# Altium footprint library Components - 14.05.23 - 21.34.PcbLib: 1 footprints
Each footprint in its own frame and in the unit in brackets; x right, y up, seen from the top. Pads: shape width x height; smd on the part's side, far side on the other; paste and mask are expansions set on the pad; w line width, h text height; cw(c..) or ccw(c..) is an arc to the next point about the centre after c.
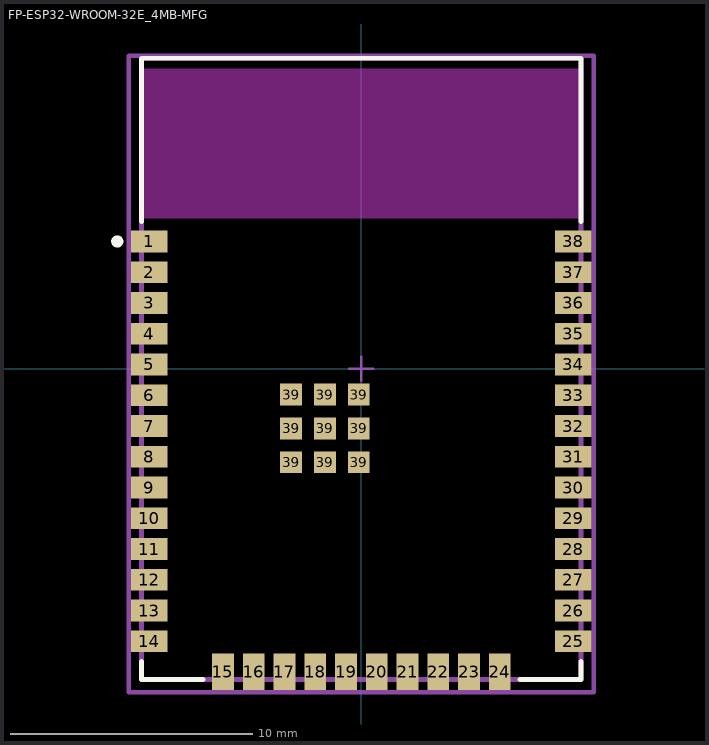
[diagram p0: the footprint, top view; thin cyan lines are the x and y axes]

## FP-ESP32-WROOM-32E_4MB-MFG [mm]
pads (47):
  rect 1.5x0.9 smd paste+0 mask+0: 1(-8.75,5.26) 2(-8.75,3.99) 3(-8.75,2.72) 4(-8.75,1.45) 5(-8.75,0.18) 6(-8.75,-1.09) 7(-8.75,-2.36) 8(-8.75,-3.63) 9(-8.75,-4.9) 10(-8.75,-6.17) 11(-8.75,-7.44) 12(-8.75,-8.71) 13(-8.75,-9.98) 14(-8.75,-11.25) 25(8.75,-11.25) 26(8.75,-9.98) 27(8.75,-8.71) 28(8.75,-7.44) 29(8.75,-6.17) 30(8.75,-4.9) 31(8.75,-3.63) 32(8.75,-2.36) 33(8.75,-1.09) 34(8.75,0.18) 35(8.75,1.45) 36(8.75,2.72) 37(8.75,3.99) 38(8.75,5.26)
  rect 0.9x1.5 smd paste+0 mask+0: 15(-5.71,-12.5) 16(-4.44,-12.5) 17(-3.17,-12.5) 18(-1.9,-12.5) 19(-0.63,-12.5) 20(0.64,-12.5) 21(1.91,-12.5) 22(3.18,-12.5) 23(4.45,-12.5) 24(5.72,-12.5)
  rect 0.9x0.9 smd paste+0 mask+0: 39(-2.9,-3.86) 39(-2.9,-2.46) 39(-2.9,-1.06) 39(-1.5,-3.86) 39(-1.5,-2.46) 39(-1.5,-1.06) 39(-0.1,-3.86) 39(-0.1,-2.46) 39(-0.1,-1.06)
Top Overlay:
  circle w0.25: c-10.075,5.26 r0.125
  lines w0.2: -9.075,-12.075 -9.075,-12.825 -6.535,-12.825 ; -9.075,6.085 -9.075,12.825 9.075,12.825 9.075,6.085 ; 6.545,-12.825 9.075,-12.825 9.075,-12.075
Keep-Out Layer:
  rectangle: -9,6.205 9,12.395
  rectangle: -9,6.205 9,12.395
Top Assembly:
  lines w0.2: -9.6,-13.35 -9.6,12.925 9.6,12.925 9.6,-13.35 -9.6,-13.35
  text ".Designator" at 0,-0.025 h1
Top 3D Body:
  lines w0.2: -9.075,-12.825 -9.075,12.825 9.075,12.825 9.075,-12.825 -9.075,-12.825
Top Courtyard:
  lines w0.2: -9.6,-13.35 -9.6,12.925 9.6,12.925 9.6,-13.35 -9.6,-13.35
Top Component Center:
  lines w0.1: -0.5,0 0.5,0 ; 0,-0.5 0,0.5
3D body "UNK_Espressif_Systems_ESP32-WROOM-32E_4MB_eec.STEP": height 0.25, standoff 0, extent -9.6,-13.35 9.6,12.925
